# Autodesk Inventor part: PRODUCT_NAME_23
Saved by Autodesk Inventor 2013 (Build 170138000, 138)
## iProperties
Created: 2012-12
Part Number: PRODUCT_NAME_23
Material: Générique
Document SubType Name: Modeling
Designer: jost thierry
Density: 1 g/cm^3
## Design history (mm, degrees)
node "PRODUCT_NAME_231"
node "PRODUCT_NAME_23"
node "Base1"
